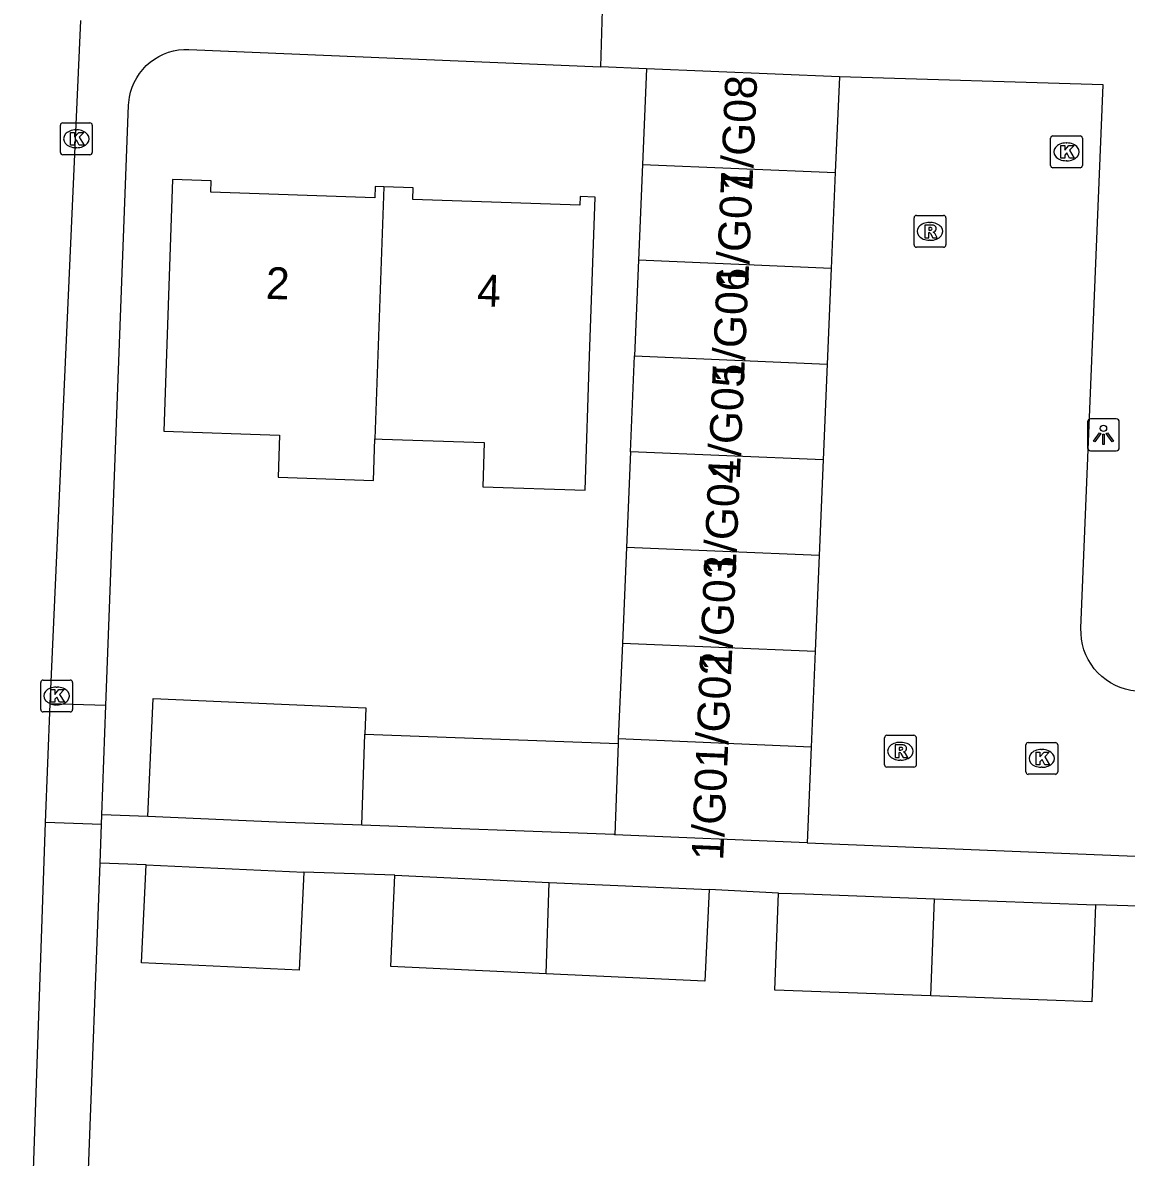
# Model space of a CAD drawing. Extents: x 161355 to 162026, y 386504 to 387459.
# Drawn here: x 161506.15 to 161540.83, y 387313.91 to 387349.56 of the extents above; entities that cross this region are included whole.
import ezdxf

# ---------------------------------------------------------------- set-up
doc = ezdxf.new("R2010")
doc.units = 0
for name, color, linetype in [('IMGEO_Kolk', 7, 'Continuous'), ('IMGEO_Lichtpunt', 7, 'Continuous'), ('IMGEO_Pand', 7, 'Continuous'), ('IMGEO_Pand_nummerreeks', 7, 'Continuous'), ('IMGEO_Rijbaan_lokaal_open', 7, 'Continuous'), ('IMGEO_Rioolput', 7, 'Continuous'), ('IMGEO_Voetpad_open', 7, 'Continuous')]:
    doc.layers.add(name, color=color, linetype=linetype)

msp = doc.modelspace()

# ---------------------------------------------------------------- linework, layer by layer
at = {"layer": 'IMGEO_Kolk'}
for p, q in [((161507.339, 387345.483), (161507.339, 387346.335)), ((161507.414, 387346.409), (161508.266, 387346.409)), ((161507.827, 387346.189), (161507.852, 387346.189)), ((161508.34, 387346.335), (161508.34, 387345.483)), ((161538.45, 387345.073), (161538.45, 387345.925)), ((161538.525, 387345.999), (161539.377, 387345.999)), ((161539.451, 387345.925), (161539.451, 387345.073)), ((161507.85, 387345.629), (161507.825, 387345.629)), ((161538.938, 387345.779), (161538.963, 387345.779)), ((161508.266, 387345.409), (161507.414, 387345.409)), ((161538.961, 387345.219), (161538.936, 387345.219)), ((161539.377, 387344.999), (161538.525, 387344.999)), ((161506.719, 387327.981), (161506.719, 387328.833)), ((161506.794, 387328.907), (161507.646, 387328.907)), ((161507.72, 387328.833), (161507.72, 387327.981)), ((161507.207, 387328.687), (161507.232, 387328.687)), ((161507.23, 387328.127), (161507.205, 387328.127)), ((161507.646, 387327.907), (161506.794, 387327.907)), ((161537.748, 387326.945), (161538.6, 387326.945)), ((161537.673, 387326.019), (161537.673, 387326.871)), ((161538.161, 387326.725), (161538.186, 387326.725)), ((161538.674, 387326.871), (161538.674, 387326.019)), ((161538.6, 387325.945), (161537.748, 387325.945)), ((161538.184, 387326.165), (161538.159, 387326.165))]:
    msp.add_line(p, q, dxfattribs=at)
for points in [[(161507.339, 387345.483), (161507.339, 387346.335)], [(161507.414, 387346.409), (161508.266, 387346.409)], [(161508.34, 387346.335), (161508.34, 387345.483)], [(161507.66, 387346.109), (161507.783, 387346.109), (161507.783, 387345.958), (161507.913, 387346.109), (161508.077, 387346.109), (161507.931, 387345.958), (161508.084, 387345.709), (161507.932, 387345.709), (161507.847, 387345.873), (161507.783, 387345.806), (161507.783, 387345.709), (161507.66, 387345.709), (161507.66, 387346.109)], [(161538.45, 387345.073), (161538.45, 387345.925)], [(161538.525, 387345.999), (161539.377, 387345.999)], [(161539.451, 387345.925), (161539.451, 387345.073)], [(161538.771, 387345.699), (161538.894, 387345.699), (161538.894, 387345.548), (161539.024, 387345.699), (161539.188, 387345.699), (161539.042, 387345.548), (161539.195, 387345.299), (161539.043, 387345.299), (161538.958, 387345.463), (161538.894, 387345.396), (161538.894, 387345.299), (161538.771, 387345.299), (161538.771, 387345.699)], [(161508.266, 387345.409), (161507.414, 387345.409)], [(161539.377, 387344.999), (161538.525, 387344.999)], [(161506.719, 387327.981), (161506.719, 387328.833)], [(161506.794, 387328.907), (161507.646, 387328.907)], [(161507.72, 387328.833), (161507.72, 387327.981)], [(161507.04, 387328.607), (161507.163, 387328.607), (161507.163, 387328.456), (161507.293, 387328.607), (161507.457, 387328.607), (161507.311, 387328.456), (161507.464, 387328.207), (161507.312, 387328.207), (161507.227, 387328.371), (161507.163, 387328.304), (161507.163, 387328.207), (161507.04, 387328.207), (161507.04, 387328.607)], [(161507.646, 387327.907), (161506.794, 387327.907)], [(161537.748, 387326.945), (161538.6, 387326.945)], [(161537.673, 387326.019), (161537.673, 387326.871)], [(161537.994, 387326.645), (161538.117, 387326.645), (161538.117, 387326.494), (161538.247, 387326.645), (161538.411, 387326.645), (161538.265, 387326.494), (161538.418, 387326.245), (161538.266, 387326.245), (161538.181, 387326.409), (161538.117, 387326.342), (161538.117, 387326.245), (161537.994, 387326.245), (161537.994, 387326.645)], [(161538.674, 387326.871), (161538.674, 387326.019)], [(161538.6, 387325.945), (161537.748, 387325.945)]]:
    msp.add_lwpolyline(points, dxfattribs=at)
for centre, start, end in [((161507.416, 387346.333), 91.552, 178.448), ((161507.416, 387346.333), 91.552, 178.448), ((161508.264, 387346.333), 1.552, 88.448), ((161508.264, 387346.333), 1.552, 88.448), ((161538.527, 387345.923), 91.552, 178.448), ((161538.527, 387345.923), 91.552, 178.448), ((161539.375, 387345.923), 1.552, 88.448), ((161539.375, 387345.923), 1.552, 88.448), ((161507.416, 387345.485), 181.552, 268.448), ((161507.416, 387345.485), 181.552, 268.448), ((161508.264, 387345.485), 271.552, 358.448), ((161508.264, 387345.485), 271.552, 358.448), ((161538.527, 387345.075), 181.552, 268.448), ((161538.527, 387345.075), 181.552, 268.448), ((161539.375, 387345.075), 271.552, 358.448), ((161539.375, 387345.075), 271.552, 358.448), ((161506.796, 387328.831), 91.552, 178.448), ((161506.796, 387328.831), 91.552, 178.448), ((161507.644, 387328.831), 1.552, 88.448), ((161507.644, 387328.831), 1.552, 88.448), ((161506.796, 387327.983), 181.552, 268.448), ((161506.796, 387327.983), 181.552, 268.448), ((161507.644, 387327.983), 271.552, 358.448), ((161507.644, 387327.983), 271.552, 358.448), ((161537.75, 387326.869), 91.552, 178.448), ((161537.75, 387326.869), 91.552, 178.448), ((161538.598, 387326.869), 1.552, 88.448), ((161538.598, 387326.869), 1.552, 88.448), ((161537.75, 387326.021), 181.552, 268.448), ((161537.75, 387326.021), 181.552, 268.448), ((161538.598, 387326.021), 271.552, 358.448), ((161538.598, 387326.021), 271.552, 358.448)]:
    msp.add_arc(centre, 0.0765, start, end, dxfattribs=at)
for centre, major_axis, ratio, start_param, end_param in [((161507.826, 387345.909), (-0.387, 0.002), 0.722429, 4.712389, 7.853982), ((161507.851, 387345.909), (-0.39, 0.002), 0.717154, 1.570796, 4.712389), ((161538.937, 387345.499), (-0.387, 0.002), 0.722429, 4.712389, 7.853982), ((161538.962, 387345.499), (-0.39, 0.002), 0.717154, 1.570796, 4.712389), ((161507.206, 387328.407), (-0.387, 0.002), 0.722429, 4.712389, 7.853982), ((161507.231, 387328.407), (-0.39, 0.002), 0.717154, 1.570796, 4.712389), ((161538.16, 387326.445), (-0.387, 0.002), 0.722429, 4.712389, 7.853982), ((161538.185, 387326.445), (-0.39, 0.002), 0.717154, 1.570796, 4.712389)]:
    msp.add_ellipse(centre, major_axis=major_axis, ratio=ratio, start_param=start_param, end_param=end_param, dxfattribs=at)
at = {"layer": 'IMGEO_Lichtpunt'}
for p, q in [((161539.613, 387337.013), (161539.613, 387336.206)), ((161539.613, 387337.013), (161539.613, 387336.206)), ((161540.515, 387337.108), (161539.707, 387337.108)), ((161540.515, 387337.108), (161539.707, 387337.108)), ((161540.609, 387336.206), (161540.609, 387337.013)), ((161540.609, 387336.206), (161540.609, 387337.013)), ((161539.707, 387336.112), (161540.515, 387336.112)), ((161539.707, 387336.112), (161540.515, 387336.112))]:
    msp.add_line(p, q, dxfattribs=at)
for points in [[(161539.987, 387336.677), (161540.026, 387336.649), (161539.838, 387336.387), (161539.8, 387336.414), (161539.987, 387336.677)], [(161540.089, 387336.629), (161540.136, 387336.629), (161540.136, 387336.307), (161540.089, 387336.307), (161540.089, 387336.629)], [(161540.199, 387336.649), (161540.237, 387336.676), (161540.424, 387336.414), (161540.385, 387336.386), (161540.199, 387336.649)]]:
    msp.add_lwpolyline(points, dxfattribs=at)
msp.add_circle((161540.112, 387336.811), 0.0994, dxfattribs=at)
for centre, start, end in [((161539.707, 387337.013), 90, 180), ((161539.707, 387337.013), 90, 180), ((161540.515, 387337.013), 0, 90), ((161540.515, 387337.013), 0, 90), ((161539.707, 387336.206), 180, 270), ((161539.707, 387336.206), 180, 270), ((161540.515, 387336.206), 270, 0), ((161540.515, 387336.206), 270, 360)]:
    msp.add_arc(centre, 0.0946, start, end, dxfattribs=at)
at = {"layer": 'IMGEO_Pand'}
for points in [[(161525.757, 387348.108), (161525.63, 387345.101)], [(161531.813, 387347.853), (161525.757, 387348.108)], [(161531.813, 387347.853), (161531.686, 387344.846)], [(161525.63, 387345.101), (161525.503, 387342.094)], [(161525.63, 387345.101), (161531.686, 387344.846)], [(161531.686, 387344.846), (161531.559, 387341.838)], [(161517.504, 387344.4), (161517.232, 387344.409), (161517.22, 387344.051), (161512.062, 387344.228), (161512.074, 387344.586), (161510.864, 387344.627), (161510.593, 387336.728), (161514.222, 387336.603), (161514.176, 387335.283), (161517.176, 387335.18), (161517.222, 387336.484)], [(161517.504, 387344.4), (161517.222, 387336.484)], [(161517.222, 387336.484), (161517.45, 387336.476), (161520.655, 387336.366), (161520.607, 387334.979), (161523.822, 387334.868), (161523.967, 387339.079), (161524.138, 387344.076), (161523.668, 387344.092), (161523.658, 387343.822), (161518.415, 387344.002), (161518.427, 387344.368), (161517.504, 387344.4)], [(161525.503, 387342.094), (161525.376, 387339.087)], [(161531.559, 387341.838), (161525.503, 387342.094)], [(161531.559, 387341.838), (161531.432, 387338.831)], [(161525.249, 387336.08), (161525.376, 387339.087)], [(161525.376, 387339.087), (161531.432, 387338.831)], [(161531.432, 387338.831), (161531.306, 387335.824)], [(161525.249, 387336.08), (161525.122, 387333.072)], [(161531.306, 387335.824), (161525.249, 387336.08)], [(161531.306, 387335.824), (161531.179, 387332.817)], [(161525.122, 387333.072), (161524.995, 387330.065)], [(161531.179, 387332.817), (161525.122, 387333.072)], [(161531.179, 387332.817), (161531.052, 387329.81)], [(161524.995, 387330.065), (161524.868, 387327.058)], [(161524.995, 387330.065), (161531.052, 387329.81)], [(161531.052, 387329.81), (161530.925, 387326.802)], [(161510.084, 387324.621), (161510.249, 387328.33), (161514.29, 387328.151), (161516.934, 387328.034), (161516.905, 387327.211)], [(161516.805, 387324.343), (161516.905, 387327.211)], [(161516.905, 387327.211), (161524.862, 387326.917)], [(161524.862, 387326.917), (161524.756, 387324.049)], [(161524.868, 387327.058), (161524.862, 387326.917)], [(161530.925, 387326.802), (161524.868, 387327.058)], [(161530.925, 387326.802), (161530.798, 387323.795)], [(161516.805, 387324.343), (161514.125, 387324.442), (161510.084, 387324.621)], [(161524.756, 387324.049), (161524.741, 387324.05), (161516.805, 387324.343)], [(161530.798, 387323.795), (161524.756, 387324.049)], [(161514.987, 387322.873), (161514.845, 387319.794), (161509.889, 387320.023), (161510.031, 387323.102)], [(161510.031, 387323.102), (161514.987, 387322.873)], [(161522.604, 387319.681), (161517.719, 387319.912), (161517.85, 387322.773)], [(161517.85, 387322.773), (161522.693, 387322.552)], [(161522.604, 387319.681), (161522.693, 387322.552)], [(161527.72, 387322.323), (161527.588, 387319.446), (161522.604, 387319.681)], [(161522.693, 387322.552), (161527.72, 387322.323)], [(161534.688, 387318.985), (161529.786, 387319.169), (161529.901, 387322.217)], [(161529.901, 387322.217), (161530.732, 387322.186), (161534.803, 387322.033)], [(161534.688, 387318.985), (161534.803, 387322.033)], [(161534.803, 387322.033), (161539.863, 387321.843)], [(161539.863, 387321.843), (161539.749, 387318.795), (161534.688, 387318.985)]]:
    msp.add_lwpolyline(points, dxfattribs=at)
at = {"layer": 'IMGEO_Rijbaan_lokaal_open'}
for points in [[(161507.019, 387328.161), (161507.982, 387349.624)], [(161561.42, 387327.893), (161561.429, 387327.686), (161541.229, 387328.551), (161541.14, 387328.557), (161540.971, 387328.58), (161540.805, 387328.618), (161540.642, 387328.67), (161540.486, 387328.737), (161540.335, 387328.818), (161540.193, 387328.912), (161540.059, 387329.018), (161539.936, 387329.135), (161539.823, 387329.263), (161539.723, 387329.401), (161539.635, 387329.547), (161539.561, 387329.701), (161539.5, 387329.86), (161539.454, 387330.024), (161539.423, 387330.192), (161539.407, 387330.361), (161539.406, 387330.532), (161540.1, 387347.609), (161531.813, 387347.853)], [(161506.872, 387324.432), (161507.019, 387328.161)], [(161506.153, 387302.221), (161506.407, 387311.079), (161506.872, 387324.432)], [(161530.798, 387323.795), (161561.221, 387322.559), (161561.219, 387322.267)]]:
    msp.add_lwpolyline(points, dxfattribs=at)
at = {"layer": 'IMGEO_Rioolput'}
for p, q in [((161534.16, 387342.574), (161534.16, 387343.426)), ((161534.235, 387343.5), (161535.087, 387343.5)), ((161535.161, 387343.426), (161535.161, 387342.574)), ((161534.648, 387343.28), (161534.673, 387343.28)), ((161534.671, 387342.72), (161534.646, 387342.72)), ((161535.087, 387342.5), (161534.235, 387342.5)), ((161533.231, 387326.244), (161533.231, 387327.096)), ((161533.306, 387327.17), (161534.158, 387327.17)), ((161533.719, 387326.95), (161533.744, 387326.95)), ((161534.232, 387327.096), (161534.232, 387326.244)), ((161533.742, 387326.39), (161533.717, 387326.39)), ((161534.158, 387326.17), (161533.306, 387326.17))]:
    msp.add_line(p, q, dxfattribs=at)
for points in [[(161534.16, 387342.574), (161534.16, 387343.426)], [(161534.235, 387343.5), (161535.087, 387343.5)], [(161535.161, 387343.426), (161535.161, 387342.574)], [(161534.749, 387343.198), (161534.497, 387343.2), (161534.497, 387342.8)], [(161534.497, 387342.8), (161534.621, 387342.8), (161534.621, 387342.962), (161534.632, 387342.962)], [(161534.675, 387343.119), (161534.621, 387343.119), (161534.621, 387343.038)], [(161534.621, 387343.038), (161534.673, 387343.038)], [(161534.679, 387342.933), (161534.75, 387342.8), (161534.89, 387342.8), (161534.825, 387342.926)], [(161535.087, 387342.5), (161534.235, 387342.5)], [(161533.231, 387326.244), (161533.231, 387327.096)], [(161533.306, 387327.17), (161534.158, 387327.17)], [(161534.232, 387327.096), (161534.232, 387326.244)], [(161533.82, 387326.868), (161533.568, 387326.87), (161533.568, 387326.47)], [(161533.568, 387326.47), (161533.692, 387326.47), (161533.692, 387326.632), (161533.703, 387326.632)], [(161533.746, 387326.789), (161533.692, 387326.789), (161533.692, 387326.708)], [(161533.692, 387326.708), (161533.744, 387326.708)], [(161533.75, 387326.603), (161533.821, 387326.47), (161533.961, 387326.47), (161533.896, 387326.596)], [(161534.158, 387326.17), (161533.306, 387326.17)]]:
    msp.add_lwpolyline(points, dxfattribs=at)
for centre, radius, start, end in [((161534.237, 387343.424), 0.0765, 91.552, 178.448), ((161534.237, 387343.424), 0.0765, 91.552, 178.448), ((161535.085, 387343.424), 0.0765, 1.552, 88.448), ((161535.085, 387343.424), 0.0765, 1.552, 88.448), ((161534.631, 387342.909), 0.0533, 26.0293, 88.6989), ((161534.657, 387343.227), 0.19, 274.7715, 282.9687), ((161534.681, 387343.023), 0.0964, 77.0061, 93.1865), ((161534.695, 387343.08), 0.0378, 276.6634, 79.6772), ((161534.748, 387343.088), 0.109, 350.3612, 89.416), ((161534.746, 387343.088), 0.112, 277.5842, 350.9817), ((161534.73, 387342.873), 0.108, 29.5134, 73.7905), ((161534.237, 387342.576), 0.0765, 181.552, 268.448), ((161534.237, 387342.576), 0.0765, 181.552, 268.448), ((161535.085, 387342.576), 0.0765, 271.552, 358.448), ((161535.085, 387342.576), 0.0765, 271.552, 358.448), ((161533.308, 387327.094), 0.0765, 91.552, 178.448), ((161533.308, 387327.094), 0.0765, 91.552, 178.448), ((161534.156, 387327.094), 0.0765, 1.552, 88.448), ((161534.156, 387327.094), 0.0765, 1.552, 88.448), ((161533.702, 387326.579), 0.0533, 26.0293, 88.6989), ((161533.728, 387326.897), 0.19, 274.7715, 282.9687), ((161533.752, 387326.693), 0.0964, 77.0061, 93.1865), ((161533.766, 387326.75), 0.0378, 276.6634, 79.6772), ((161533.819, 387326.758), 0.109, 350.3612, 89.416), ((161533.817, 387326.758), 0.112, 277.5842, 350.9817), ((161533.801, 387326.543), 0.108, 29.5134, 73.7905), ((161533.308, 387326.246), 0.0765, 181.552, 268.448), ((161533.308, 387326.246), 0.0765, 181.552, 268.448), ((161534.156, 387326.246), 0.0765, 271.552, 358.448), ((161534.156, 387326.246), 0.0765, 271.552, 358.448)]:
    msp.add_arc(centre, radius, start, end, dxfattribs=at)
for centre, major_axis, ratio, start_param, end_param in [((161534.647, 387343), (-0.387, 0.002), 0.722429, 4.712389, 7.853982), ((161534.672, 387343), (-0.39, 0.002), 0.717154, 1.570796, 4.712389), ((161533.718, 387326.67), (-0.387, 0.002), 0.722429, 4.712389, 7.853982), ((161533.743, 387326.67), (-0.39, 0.002), 0.717154, 1.570796, 4.712389)]:
    msp.add_ellipse(centre, major_axis=major_axis, ratio=ratio, start_param=start_param, end_param=end_param, dxfattribs=at)
at = {"layer": 'IMGEO_Voetpad_open'}
for points in [[(161524.316, 387348.169), (161524.391, 387350.667)], [(161508.77, 387328.112), (161509.48, 387346.96), (161509.486, 387347.054), (161509.508, 387347.215), (161509.544, 387347.375), (161509.594, 387347.53), (161509.658, 387347.68), (161509.735, 387347.824), (161509.824, 387347.961), (161509.926, 387348.089), (161510.038, 387348.207), (161510.161, 387348.315), (161510.292, 387348.412), (161510.432, 387348.496), (161510.579, 387348.568), (161510.731, 387348.626), (161510.889, 387348.67), (161511.049, 387348.7), (161511.212, 387348.716), (161511.375, 387348.717), (161524.316, 387348.169)], [(161525.757, 387348.108), (161524.316, 387348.169)], [(161508.77, 387328.112), (161507.019, 387328.161)], [(161508.64, 387324.668), (161508.77, 387328.112)], [(161508.629, 387324.365), (161506.872, 387324.432)], [(161508.629, 387324.365), (161508.64, 387324.668)], [(161510.084, 387324.621), (161508.64, 387324.668)], [(161508.583, 387323.155), (161508.629, 387324.365)], [(161507.816, 387302.794), (161508.583, 387323.155)], [(161510.031, 387323.102), (161508.583, 387323.155)], [(161517.85, 387322.773), (161514.987, 387322.873)], [(161529.901, 387322.217), (161527.72, 387322.323)], [(161542.226, 387321.771), (161539.863, 387321.843)]]:
    msp.add_lwpolyline(points, dxfattribs=at)

# ---------------------------------------------------------------- texts
at = {"layer": 'IMGEO_Pand_nummerreeks'}
for s, rotation, p in [('1/G08', 87.5104, (161529.076, 387344.239)), ('1/G07', 87.5104, (161528.945, 387341.219)), ('2', 358.0004, (161513.779, 387340.885)), ('4', 358.0004, (161520.419, 387340.654)), ('1/G06', 87.5104, (161528.814, 387338.202)), ('1/G05', 87.5104, (161528.683, 387335.185)), ('1/G04', 87.5104, (161528.552, 387332.168)), ('1/G03', 87.5104, (161528.42, 387329.151)), ('1/G02', 87.5104, (161528.289, 387326.127)), ('1/G01', 87.5104, (161528.163, 387323.227))]:
    msp.add_text(s, height=1, rotation=rotation, dxfattribs=at).set_placement(p)

doc.saveas('drawing.dxf')
